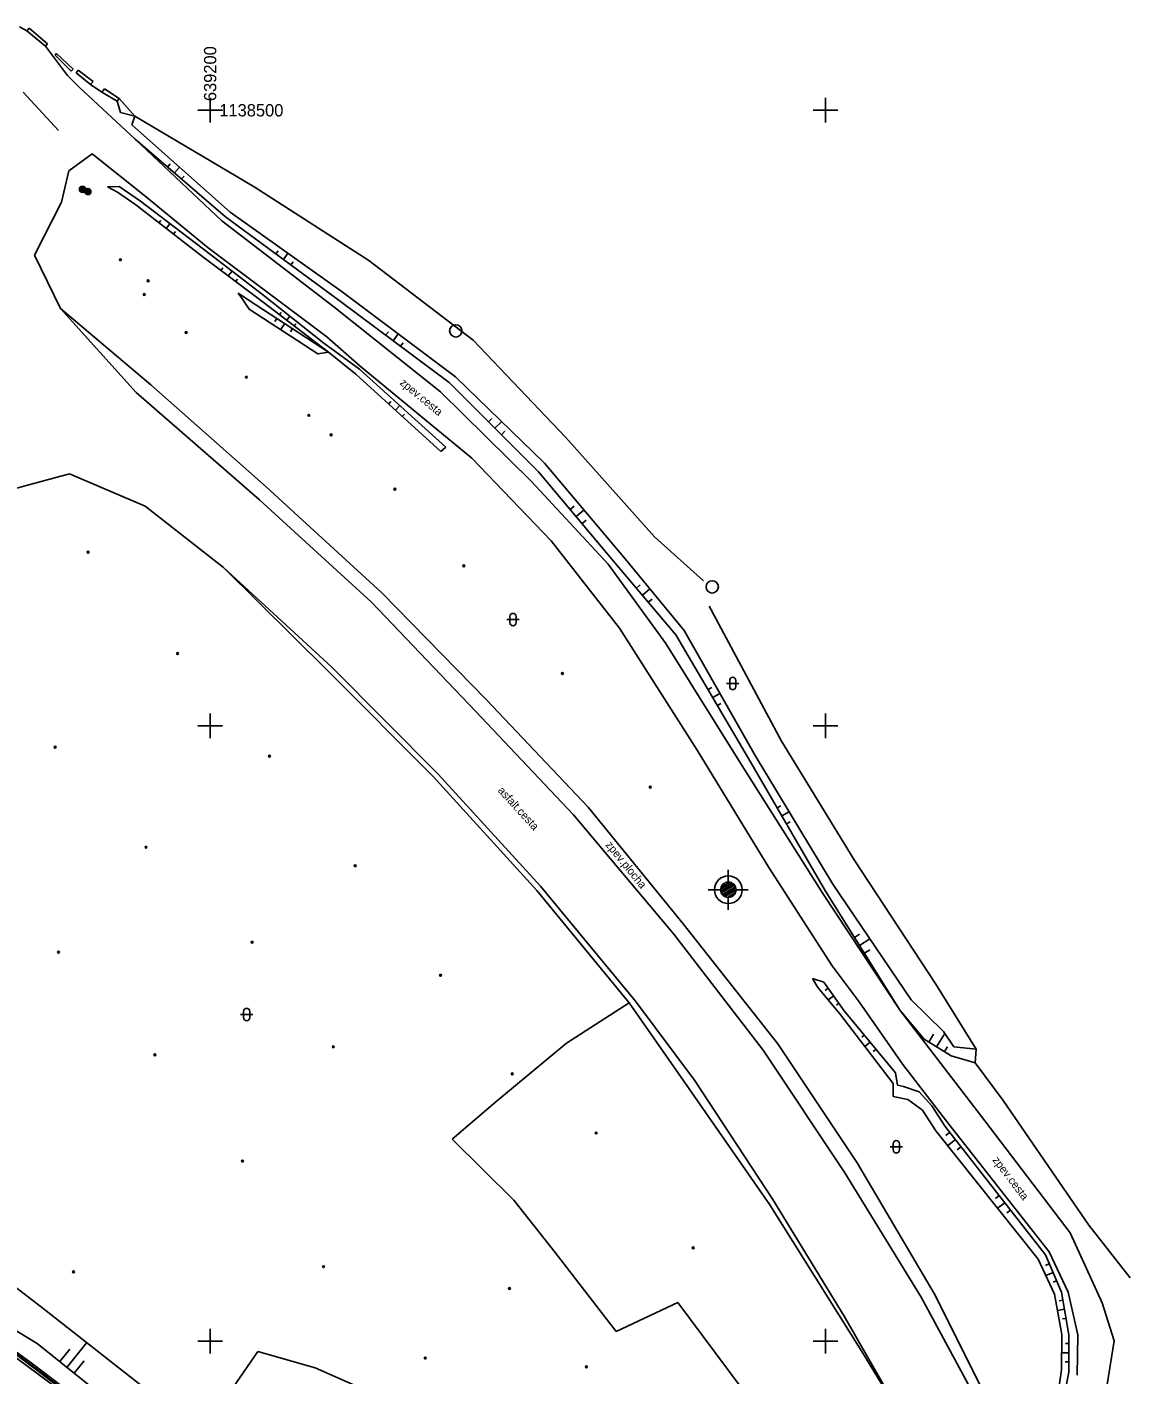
# Model space of a CAD drawing. Extents: x -639440 to -639026, y -1138850 to -1138262.
# Drawn here: x -639214.9 to -639125.9, y -1138602.7 to -1138493.2 of the extents above; entities that cross this region are included whole.
import ezdxf

# ---------------------------------------------------------------- set-up
doc = ezdxf.new("R2010")
doc.units = 0
for name, color, linetype in [('Vrstva 10', 7, 'Continuous'), ('Vrstva 11', 7, 'Continuous'), ('Vrstva 14', 7, 'Continuous'), ('Vrstva 15', 7, 'Continuous'), ('Vrstva 20', 7, 'Continuous'), ('Vrstva 23', 7, 'Continuous'), ('Vrstva 25', 7, 'Continuous'), ('Vrstva 27', 7, 'Continuous'), ('Vrstva 35', 7, 'Continuous'), ('Vrstva 36', 7, 'Continuous'), ('Vrstva 40', 7, 'Continuous'), ('Vrstva 58', 7, 'Continuous'), ('Vrstva 61', 7, 'Continuous'), ('Vrstva 7', 7, 'Continuous')]:
    doc.layers.add(name, color=color, linetype=linetype)

msp = doc.modelspace()

# ---------------------------------------------------------------- linework, layer by layer
at = {"layer": 'Vrstva 10'}
for p, q in [((-639215.48, -1138493.23), (-639214.88, -1138493.55)), ((-639214.88, -1138493.55), (-639213.38, -1138494.78)), ((-639213.38, -1138494.78), (-639211.58, -1138497.17)), ((-639211.58, -1138497.17), (-639210.63, -1138498.13)), ((-639210.63, -1138498.13), (-639206.08, -1138502.35)), ((-639206.08, -1138502.35), (-639199.05, -1138508.98)), ((-639209.58, -1138503.55), (-639211.49, -1138504.93)), ((-639205.3, -1138506.94), (-639209.58, -1138503.55)), ((-639211.49, -1138504.93), (-639212.07, -1138507.47)), ((-639212.07, -1138507.47), (-639214.27, -1138511.78)), ((-639200.16, -1138511.18), (-639205.3, -1138506.94)), ((-639199.05, -1138508.98), (-639189.95, -1138515.96)), ((-639214.27, -1138511.78), (-639212.15, -1138516.09)), ((-639190.53, -1138518.4), (-639200.16, -1138511.18)), ((-639212.15, -1138516.09), (-639206.02, -1138522.92)), ((-639189.95, -1138515.96), (-639181.28, -1138522.87)), ((-639187.8, -1138520.78), (-639190.53, -1138518.4)), ((-639178.73, -1138528.27), (-639187.8, -1138520.78)), ((-639206.02, -1138522.92), (-639195.99, -1138531.64)), ((-639181.28, -1138522.87), (-639173.89, -1138530.15)), ((-639172.29, -1138534.98), (-639178.73, -1138528.27)), ((-639211.43, -1138529.52), (-639218.24, -1138531.37)), ((-639205.27, -1138532.15), (-639211.43, -1138529.52)), ((-639173.89, -1138530.15), (-639167.67, -1138536.86)), ((-639198.92, -1138537.15), (-639205.27, -1138532.15)), ((-639195.99, -1138531.64), (-639186.89, -1138539.97)), ((-639166.75, -1138542.08), (-639172.29, -1138534.98)), ((-639167.67, -1138536.86), (-639162.97, -1138543.32)), ((-639190.1, -1138545.23), (-639198.92, -1138537.15)), ((-639186.89, -1138539.97), (-639178.43, -1138548.8)), ((-639160.44, -1138551.98), (-639166.75, -1138542.08)), ((-639162.97, -1138543.32), (-639156.9, -1138553.03)), ((-639181.47, -1138553.92), (-639190.1, -1138545.23)), ((-639178.43, -1138548.8), (-639170.48, -1138557.24)), ((-639154.62, -1138561.52), (-639160.44, -1138551.98)), ((-639156.9, -1138553.03), (-639150.22, -1138563.63)), ((-639173.16, -1138563.02), (-639181.47, -1138553.92)), ((-639170.48, -1138557.24), (-639162.34, -1138566.94)), ((-639149.45, -1138569.5), (-639154.62, -1138561.52)), ((-639165.45, -1138572.36), (-639173.16, -1138563.02)), ((-639150.22, -1138563.63), (-639143.93, -1138573.13)), ((-639162.34, -1138566.94), (-639155.06, -1138576.36)), ((-639147.28, -1138572.42), (-639149.45, -1138569.5)), ((-639160.65, -1138578.79), (-639165.45, -1138572.36)), ((-639143.73, -1138577.51), (-639147.28, -1138572.42)), ((-639143.93, -1138573.13), (-639137.06, -1138582.09)), ((-639155.06, -1138576.36), (-639148.43, -1138586.32)), ((-639139.98, -1138582.35), (-639143.73, -1138577.51)), ((-639154.29, -1138588.47), (-639160.65, -1138578.79)), ((-639131.83, -1138592.74), (-639139.98, -1138582.35)), ((-639137.06, -1138582.09), (-639130.12, -1138591.2)), ((-639148.43, -1138586.32), (-639142.24, -1138596.43)), ((-639148.48, -1138597.96), (-639154.29, -1138588.47)), ((-639130.12, -1138591.2), (-639127.53, -1138596.88)), ((-639130.29, -1138596), (-639131.83, -1138592.74)), ((-639129.5, -1138599.47), (-639130.29, -1138596)), ((-639142.24, -1138596.43), (-639136.62, -1138606.78)), ((-639127.53, -1138596.88), (-639126.56, -1138599.96)), ((-639143.51, -1138606.64), (-639148.48, -1138597.96)), ((-639129.57, -1138602.75), (-639129.5, -1138599.47)), ((-639126.56, -1138599.96), (-639127.11, -1138603.5))]:
    msp.add_line(p, q, dxfattribs=at)
at = {"layer": 'Vrstva 11'}
for p, q in [((-639214.69, -1138493.33), (-639214.88, -1138493.55)), ((-639214.69, -1138493.33), (-639213.21, -1138494.61)), ((-639213.21, -1138494.61), (-639213.38, -1138494.78)), ((-639212.6, -1138495.51), (-639212.48, -1138495.38)), ((-639212.48, -1138495.38), (-639211.13, -1138496.65)), ((-639211.3, -1138496.82), (-639212.6, -1138495.51)), ((-639211.13, -1138496.65), (-639211.3, -1138496.82)), ((-639210.88, -1138496.95), (-639210.71, -1138496.73)), ((-639209.71, -1138497.9), (-639210.88, -1138496.95)), ((-639210.71, -1138496.73), (-639209.51, -1138497.66)), ((-639209.51, -1138497.66), (-639209.71, -1138497.9)), ((-639208.79, -1138498.54), (-639208.58, -1138498.25)), ((-639208.58, -1138498.25), (-639207.38, -1138499.05)), ((-639207.38, -1138499.05), (-639207.56, -1138499.27)), ((-639165.96, -1138572.52), (-639171.06, -1138575.78)), ((-639171.06, -1138575.78), (-639176.79, -1138580.56)), ((-639176.79, -1138580.56), (-639180.33, -1138583.57)), ((-639180.33, -1138583.57), (-639175.33, -1138588.55)), ((-639175.33, -1138588.55), (-639171.97, -1138592.8)), ((-639171.97, -1138592.8), (-639167.02, -1138599.2)), ((-639167.02, -1138599.2), (-639162, -1138596.86)), ((-639162, -1138596.86), (-639153.43, -1138608.35)), ((-639214.65, -1138601.66), (-639218.03, -1138599.22)), ((-639196.13, -1138600.83), (-639198.4, -1138604.13)), ((-639191.46, -1138602.15), (-639196.13, -1138600.83)), ((-639205.13, -1138608.87), (-639214.65, -1138601.66)), ((-639184.91, -1138605.05), (-639191.46, -1138602.15))]:
    msp.add_line(p, q, dxfattribs=at)
at = {"layer": 'Vrstva 14'}
for p, q in [((-639209.71, -1138497.9), (-639208.79, -1138498.54)), ((-639208.79, -1138498.54), (-639207.56, -1138499.27)), ((-639207.56, -1138499.27), (-639207.27, -1138500.17)), ((-639206.13, -1138500.48), (-639207.38, -1138499.05)), ((-639207.27, -1138500.17), (-639206.13, -1138500.48)), ((-639206.13, -1138500.48), (-639206.36, -1138501.18)), ((-639206.13, -1138500.48), (-639196.43, -1138506.23)), ((-639206.36, -1138501.18), (-639198.37, -1138508.27)), ((-639206.08, -1138502.35), (-639198.75, -1138508.66)), ((-639207.39, -1138506.2), (-639208.34, -1138506.21)), ((-639207.53, -1138506.64), (-639208.34, -1138506.21)), ((-639205.67, -1138507.38), (-639207.39, -1138506.2)), ((-639196.43, -1138506.23), (-639187.11, -1138512.21)), ((-639206.03, -1138507.68), (-639207.53, -1138506.64)), ((-639200.08, -1138511.63), (-639205.67, -1138507.38)), ((-639200.6, -1138511.91), (-639206.03, -1138507.68)), ((-639198.37, -1138508.27), (-639189.26, -1138514.75)), ((-639198.75, -1138508.66), (-639189.53, -1138515.45)), ((-639195.75, -1138514.97), (-639200.08, -1138511.63)), ((-639195.68, -1138515.6), (-639200.6, -1138511.91)), ((-639187.11, -1138512.21), (-639178.63, -1138518.67)), ((-639196.29, -1138515.8), (-639197.71, -1138514.85)), ((-639197.43, -1138515.26), (-639197.71, -1138514.85)), ((-639190.77, -1138518.91), (-639195.75, -1138514.97)), ((-639189.26, -1138514.75), (-639180.06, -1138521.64)), ((-639196.83, -1138516.17), (-639197.43, -1138515.26)), ((-639191.26, -1138519.79), (-639196.83, -1138516.17)), ((-639190.37, -1138519.64), (-639196.29, -1138515.8)), ((-639190.37, -1138519.64), (-639195.68, -1138515.6)), ((-639189.53, -1138515.45), (-639180.58, -1138522.11)), ((-639187.87, -1138521.04), (-639190.77, -1138518.91)), ((-639178.63, -1138518.67), (-639171.09, -1138526.58)), ((-639190.37, -1138519.64), (-639191.26, -1138519.79)), ((-639188.15, -1138521.43), (-639190.37, -1138519.64)), ((-639181.27, -1138527.73), (-639188.15, -1138521.43)), ((-639180.85, -1138527.36), (-639187.87, -1138521.04)), ((-639180.06, -1138521.64), (-639172.83, -1138528.66)), ((-639180.58, -1138522.11), (-639173.32, -1138529.38)), ((-639171.09, -1138526.58), (-639163.89, -1138534.66)), ((-639180.85, -1138527.36), (-639181.27, -1138527.73)), ((-639172.83, -1138528.66), (-639166.27, -1138536.44)), ((-639173.32, -1138529.38), (-639167.22, -1138536.63)), ((-639163.89, -1138534.66), (-639159.91, -1138538.23)), ((-639167.22, -1138536.63), (-639162.16, -1138542.61)), ((-639166.27, -1138536.44), (-639161.49, -1138542.27)), ((-639190.4, -1138545.56), (-639198.92, -1138537.15)), ((-639159.45, -1138540.27), (-639159.3, -1138540.59)), ((-639159.3, -1138540.59), (-639153.57, -1138551.26)), ((-639161.49, -1138542.27), (-639155.71, -1138552.41)), ((-639162.16, -1138542.61), (-639156.25, -1138552.66)), ((-639181.87, -1138554.11), (-639190.4, -1138545.56)), ((-639153.57, -1138551.26), (-639147.68, -1138560.89)), ((-639156.25, -1138552.66), (-639150, -1138563.43)), ((-639155.71, -1138552.41), (-639149.41, -1138562.87)), ((-639173.47, -1138563.39), (-639181.87, -1138554.11)), ((-639147.68, -1138560.89), (-639141.03, -1138570.98)), ((-639149.41, -1138562.87), (-639143.04, -1138572.25)), ((-639165.96, -1138572.52), (-639173.47, -1138563.39)), ((-639150, -1138563.43), (-639143.93, -1138573.13)), ((-639150.13, -1138570.82), (-639151.07, -1138570.54)), ((-639150.63, -1138571.26), (-639151.07, -1138570.54)), ((-639148.48, -1138573.15), (-639150.13, -1138570.82)), ((-639148.84, -1138573.4), (-639150.63, -1138571.26)), ((-639141.03, -1138570.98), (-639137.76, -1138576.28)), ((-639161.96, -1138578.25), (-639165.96, -1138572.52)), ((-639143.93, -1138573.13), (-639142, -1138575.46)), ((-639143.04, -1138572.25), (-639140.43, -1138574.83)), ((-639144.52, -1138579.06), (-639148.84, -1138573.4)), ((-639144.31, -1138578.19), (-639148.48, -1138573.15)), ((-639140.43, -1138574.83), (-639139.57, -1138576.08)), ((-639142, -1138575.46), (-639139.79, -1138576.81)), ((-639139.57, -1138576.08), (-639137.76, -1138576.28)), ((-639137.76, -1138576.28), (-639137.84, -1138577.39)), ((-639139.79, -1138576.81), (-639137.84, -1138577.39)), ((-639137.84, -1138577.39), (-639135.57, -1138580.44)), ((-639154.53, -1138588.91), (-639161.96, -1138578.25)), ((-639144.15, -1138579.2), (-639144.31, -1138578.19)), ((-639144.51, -1138580.11), (-639144.52, -1138579.06)), ((-639143.66, -1138579.29), (-639144.15, -1138579.2)), ((-639143.66, -1138579.29), (-639142.39, -1138579.74)), ((-639144.51, -1138580.11), (-639143.31, -1138580.37)), ((-639143.31, -1138580.37), (-639142.13, -1138581.23)), ((-639142.39, -1138579.74), (-639141.36, -1138580.88)), ((-639135.57, -1138580.44), (-639128.62, -1138590.56)), ((-639142.13, -1138581.23), (-639141.05, -1138582.91)), ((-639140.29, -1138582.55), (-639141.36, -1138580.88)), ((-639132.72, -1138593.34), (-639141.05, -1138582.91)), ((-639132.14, -1138592.97), (-639140.29, -1138582.55)), ((-639147.06, -1138600.83), (-639154.53, -1138588.91)), ((-639128.62, -1138590.56), (-639125.26, -1138594.84)), ((-639213.7, -1138597.22), (-639221.6, -1138591.2)), ((-639131.41, -1138596.17), (-639132.72, -1138593.34)), ((-639130.83, -1138596), (-639132.14, -1138592.97)), ((-639130.23, -1138599.48), (-639130.83, -1138596)), ((-639130.79, -1138599.45), (-639131.41, -1138596.17)), ((-639202.39, -1138606.09), (-639213.7, -1138597.22)), ((-639216.32, -1138598.81), (-639214.05, -1138600.18)), ((-639214.05, -1138600.18), (-639204.07, -1138608.17)), ((-639130.82, -1138602.31), (-639130.79, -1138599.45)), ((-639130.23, -1138602.51), (-639130.23, -1138599.48)), ((-639143.51, -1138606.64), (-639147.06, -1138600.83)), ((-639131.57, -1138607.38), (-639130.82, -1138602.31)), ((-639131.22, -1138607.47), (-639130.23, -1138602.51))]:
    msp.add_line(p, q, dxfattribs=at)
at = {"layer": 'Vrstva 15'}
for p, q in [((-639203.46, -1138504.61), (-639203.25, -1138504.36)), ((-639202.89, -1138505.09), (-639202.48, -1138504.62)), ((-639202.32, -1138505.58), (-639202.12, -1138505.35)), ((-639204.16, -1138509.14), (-639204.01, -1138508.95)), ((-639203.57, -1138509.6), (-639203.26, -1138509.21)), ((-639202.97, -1138510.06), (-639202.82, -1138509.86)), ((-639194.66, -1138511.67), (-639194.47, -1138511.42)), ((-639194.05, -1138512.12), (-639193.68, -1138511.61)), ((-639199.13, -1138513.01), (-639198.97, -1138512.81)), ((-639193.45, -1138512.56), (-639193.26, -1138512.3)), ((-639198.53, -1138513.46), (-639198.22, -1138513.06)), ((-639197.93, -1138513.91), (-639197.78, -1138513.72)), ((-639194.57, -1138516.91), (-639194.74, -1138517.17)), ((-639194.36, -1138516.6), (-639194.24, -1138516.44)), ((-639193.94, -1138517.32), (-639194.27, -1138517.83)), ((-639193.77, -1138517.06), (-639193.52, -1138516.73)), ((-639193.31, -1138517.73), (-639193.48, -1138517.99)), ((-639193.17, -1138517.51), (-639193.05, -1138517.35)), ((-639185.74, -1138518.27), (-639185.52, -1138517.99)), ((-639185.13, -1138518.72), (-639184.71, -1138518.16)), ((-639184.53, -1138519.17), (-639184.32, -1138518.89)), ((-639185.49, -1138523.86), (-639185.32, -1138523.67)), ((-639184.94, -1138524.37), (-639184.59, -1138523.99)), ((-639184.39, -1138524.87), (-639184.21, -1138524.68)), ((-639177.39, -1138525.3), (-639177.12, -1138525.03)), ((-639176.86, -1138525.83), (-639176.31, -1138525.28)), ((-639176.33, -1138526.36), (-639176.05, -1138526.08)), ((-639170.75, -1138532.43), (-639170.43, -1138532.16)), ((-639170.27, -1138533.01), (-639169.62, -1138532.46)), ((-639169.78, -1138533.58), (-639169.46, -1138533.31)), ((-639165.37, -1138538.82), (-639165.06, -1138538.56)), ((-639164.88, -1138539.39), (-639164.27, -1138538.88)), ((-639164.4, -1138539.97), (-639164.1, -1138539.71)), ((-639159.54, -1138547.06), (-639159.25, -1138546.89)), ((-639159.16, -1138547.71), (-639158.58, -1138547.37)), ((-639158.78, -1138548.35), (-639158.5, -1138548.19)), ((-639153.92, -1138556.67), (-639153.64, -1138556.5)), ((-639153.55, -1138557.32), (-639152.96, -1138556.98)), ((-639153.17, -1138557.97), (-639152.87, -1138557.79)), ((-639147.64, -1138567.2), (-639147.23, -1138566.94)), ((-639147.24, -1138567.84), (-639146.4, -1138567.31)), ((-639146.84, -1138568.47), (-639146.41, -1138568.2)), ((-639149.78, -1138571.32), (-639150.03, -1138571.5)), ((-639149.34, -1138571.93), (-639149.8, -1138572.25)), ((-639148.91, -1138572.54), (-639149.11, -1138572.69)), ((-639146.85, -1138575.12), (-639147.06, -1138575.29)), ((-639141.62, -1138575.69), (-639141.23, -1138575.06)), ((-639140.98, -1138576.08), (-639140.32, -1138575)), ((-639146.37, -1138575.7), (-639146.81, -1138576.06)), ((-639145.89, -1138576.28), (-639146.12, -1138576.47)), ((-639140.34, -1138576.47), (-639140.1, -1138576.07)), ((-639139.92, -1138583.03), (-639140.24, -1138583.28)), ((-639139.45, -1138583.62), (-639140.09, -1138584.12)), ((-639138.99, -1138584.21), (-639139.31, -1138584.46)), ((-639135.9, -1138588.16), (-639136.2, -1138588.39)), ((-639135.44, -1138588.75), (-639136.02, -1138589.2)), ((-639134.98, -1138589.34), (-639135.27, -1138589.56)), ((-639131.82, -1138593.71), (-639132.12, -1138593.84)), ((-639131.52, -1138594.4), (-639132.11, -1138594.65)), ((-639131.23, -1138595.09), (-639131.51, -1138595.21)), ((-639130.72, -1138596.66), (-639131.01, -1138596.71)), ((-639130.59, -1138597.4), (-639131.16, -1138597.5)), ((-639130.46, -1138598.14), (-639130.74, -1138598.19)), ((-639211.63, -1138602.12), (-639210.02, -1138600.11)), ((-639130.23, -1138600.18), (-639130.51, -1138600.18)), ((-639212.22, -1138601.65), (-639211.41, -1138600.65)), ((-639211.04, -1138602.59), (-639210.24, -1138601.58)), ((-639130.23, -1138600.93), (-639130.81, -1138600.93)), ((-639130.23, -1138601.68), (-639130.52, -1138601.68))]:
    msp.add_line(p, q, dxfattribs=at)
at = {"layer": 'Vrstva 20'}
for centre, radius in [((-639207.29, -1138512.14), 0.075), ((-639207.29, -1138512.14), 0.0204), ((-639205.04, -1138513.85), 0.075), ((-639205.04, -1138513.85), 0.0204), ((-639205.35, -1138514.97), 0.075), ((-639205.35, -1138514.97), 0.0204), ((-639201.95, -1138518.05), 0.075), ((-639201.95, -1138518.05), 0.0204), ((-639197.06, -1138521.68), 0.075), ((-639197.06, -1138521.68), 0.0204), ((-639191.98, -1138524.78), 0.075), ((-639191.98, -1138524.78), 0.0204), ((-639190.17, -1138526.37), 0.075), ((-639190.17, -1138526.37), 0.0204), ((-639184.99, -1138530.78), 0.075), ((-639184.99, -1138530.78), 0.0204), ((-639209.92, -1138535.9), 0.075), ((-639209.92, -1138535.9), 0.0204), ((-639179.39, -1138537), 0.075), ((-639179.39, -1138537), 0.0204), ((-639202.64, -1138544.13), 0.075), ((-639202.64, -1138544.13), 0.0204), ((-639171.38, -1138545.75), 0.075), ((-639171.38, -1138545.75), 0.0204), ((-639212.59, -1138551.74), 0.075), ((-639212.59, -1138551.74), 0.0204), ((-639195.18, -1138552.47), 0.075), ((-639195.18, -1138552.47), 0.0204), ((-639164.24, -1138554.98), 0.075), ((-639164.24, -1138554.98), 0.0204), ((-639205.21, -1138559.87), 0.075), ((-639205.21, -1138559.87), 0.0204), ((-639188.21, -1138561.37), 0.075), ((-639188.21, -1138561.37), 0.0204), ((-639196.59, -1138567.59), 0.075), ((-639196.59, -1138567.59), 0.0204), ((-639212.32, -1138568.39), 0.075), ((-639212.32, -1138568.39), 0.0204), ((-639181.28, -1138570.27), 0.075), ((-639181.28, -1138570.27), 0.0204), ((-639189.99, -1138576.08), 0.075), ((-639189.99, -1138576.08), 0.0204), ((-639204.49, -1138576.73), 0.075), ((-639204.49, -1138576.73), 0.0204), ((-639175.45, -1138578.28), 0.075), ((-639175.45, -1138578.28), 0.0204), ((-639168.63, -1138583.08), 0.075), ((-639168.63, -1138583.08), 0.0204), ((-639197.37, -1138585.36), 0.075), ((-639197.37, -1138585.36), 0.0204), ((-639160.75, -1138592.41), 0.075), ((-639160.75, -1138592.41), 0.0204), ((-639190.78, -1138593.94), 0.075), ((-639190.78, -1138593.94), 0.0204), ((-639211.1, -1138594.36), 0.075), ((-639211.1, -1138594.36), 0.0204), ((-639175.68, -1138595.71), 0.075), ((-639175.68, -1138595.71), 0.0204), ((-639182.52, -1138601.36), 0.075), ((-639182.52, -1138601.36), 0.0204), ((-639169.43, -1138602.08), 0.075), ((-639169.43, -1138602.08), 0.0204)]:
    msp.add_circle(centre, radius, dxfattribs=at)
at = {"layer": 'Vrstva 23'}
for p, q in [((-639212.15, -1138516.09), (-639204.81, -1138522.29)), ((-639204.81, -1138522.29), (-639195.44, -1138530.6)), ((-639195.44, -1138530.6), (-639186.06, -1138539.2)), ((-639186.06, -1138539.2), (-639177.56, -1138547.89)), ((-639177.56, -1138547.89), (-639169.28, -1138556.61)), ((-639169.28, -1138556.61), (-639161.58, -1138566.09)), ((-639161.58, -1138566.09), (-639153.89, -1138575.84)), ((-639153.89, -1138575.84), (-639147.44, -1138585.5)), ((-639147.44, -1138585.5), (-639141.18, -1138596.13)), ((-639141.18, -1138596.13), (-639136.06, -1138606.3))]:
    msp.add_line(p, q, dxfattribs=at)
at = {"layer": 'Vrstva 25'}
for centre, radius in [((-639210.37, -1138506.43), 0.25), ((-639210.37, -1138506.43), 0.2), ((-639210.37, -1138506.43), 0.15), ((-639210.37, -1138506.43), 0.1), ((-639210.37, -1138506.43), 0.05), ((-639209.93, -1138506.6), 0.25), ((-639209.93, -1138506.6), 0.2), ((-639209.93, -1138506.6), 0.15), ((-639209.93, -1138506.6), 0.1), ((-639209.93, -1138506.6), 0.05)]:
    msp.add_circle(centre, radius, dxfattribs=at)
at = {"layer": 'Vrstva 27'}
for centre in [(-639180.04, -1138517.92), (-639159.21, -1138538.72)]:
    msp.add_circle(centre, 0.5, dxfattribs=at)
at = {"layer": 'Vrstva 35'}
for p, q in [((-639157.9, -1138562.7), (-639157.9, -1138561.7)), ((-639158.52, -1138563.28), (-639157.62, -1138562.76)), ((-639158.51, -1138563.44), (-639157.49, -1138562.85)), ((-639158.48, -1138563.1), (-639157.8, -1138562.7)), ((-639158.47, -1138563.57), (-639157.39, -1138562.95)), ((-639158.4, -1138563.7), (-639157.33, -1138563.07)), ((-639158.3, -1138563.8), (-639157.29, -1138563.21)), ((-639158.53, -1138563.32), (-639159.53, -1138563.32)), ((-639158.17, -1138563.88), (-639157.28, -1138563.37)), ((-639157.98, -1138563.94), (-639157.32, -1138563.56)), ((-639157.9, -1138563.95), (-639157.9, -1138564.95)), ((-639157.28, -1138563.32), (-639156.28, -1138563.32))]:
    msp.add_line(p, q, dxfattribs=at)
for radius in [1.12, 0.625]:
    msp.add_circle((-639157.9, -1138563.32), radius, dxfattribs=at)
at = {"layer": 'Vrstva 36'}
for p, q in [((-639175.89, -1138541.37), (-639174.89, -1138541.37)), ((-639175.64, -1138541.12), (-639175.64, -1138541.62)), ((-639175.14, -1138541.12), (-639175.14, -1138541.62)), ((-639158.04, -1138546.56), (-639157.04, -1138546.56)), ((-639157.79, -1138546.31), (-639157.79, -1138546.81)), ((-639157.29, -1138546.31), (-639157.29, -1138546.81)), ((-639197.53, -1138573.46), (-639196.53, -1138573.46)), ((-639197.28, -1138573.21), (-639197.28, -1138573.71)), ((-639196.78, -1138573.21), (-639196.78, -1138573.71)), ((-639144.5, -1138583.95), (-639144.5, -1138584.45)), ((-639144, -1138583.95), (-639144, -1138584.45)), ((-639144.75, -1138584.2), (-639143.75, -1138584.2))]:
    msp.add_line(p, q, dxfattribs=at)
for centre, start, end in [((-639175.39, -1138541.12), 0, 180), ((-639175.39, -1138541.62), 180, 0), ((-639157.54, -1138546.31), 0, 180), ((-639157.54, -1138546.81), 180, 0), ((-639197.03, -1138573.21), 0, 180), ((-639197.03, -1138573.71), 180, 0), ((-639144.25, -1138583.95), 0, 180), ((-639144.25, -1138584.45), 180, 0)]:
    msp.add_arc(centre, 0.25, start, end, dxfattribs=at)
at = {"layer": 'Vrstva 58'}
msp.add_line((-639215.19, -1138498.54), (-639212.32, -1138501.63), dxfattribs=at)
at = {"layer": 'Vrstva 61'}
for p, q in [((-639200, -1138499), (-639200, -1138501)), ((-639150, -1138499), (-639150, -1138501)), ((-639201, -1138500), (-639199, -1138500)), ((-639151, -1138500), (-639149, -1138500)), ((-639200, -1138549), (-639200, -1138551)), ((-639150, -1138549), (-639150, -1138551)), ((-639201, -1138550), (-639199, -1138550)), ((-639151, -1138550), (-639149, -1138550)), ((-639200, -1138599), (-639200, -1138601)), ((-639150, -1138599), (-639150, -1138601)), ((-639201, -1138600), (-639199, -1138600)), ((-639151, -1138600), (-639149, -1138600))]:
    msp.add_line(p, q, dxfattribs=at)
at = {"layer": 'Vrstva 7'}
for p, q in [((-639210.94, -1138604.92), (-639216.37, -1138600.89)), ((-639190.04, -1138620.41), (-639216.21, -1138600.66)), ((-639210.95, -1138604.73), (-639216.2, -1138600.75))]:
    msp.add_line(p, q, dxfattribs=at)

# ---------------------------------------------------------------- texts
at = {"layer": 'Vrstva 40'}
for s, rotation, p in [('zpev.cesta', 320.4501, (-639184.64, -1138522.22)), ('asfalt.cesta', 312.4019, (-639176.67, -1138555.3)), ('zpev.plocha', 309.0848, (-639167.91, -1138559.69)), ('zpev.cesta', 307.3002, (-639136.47, -1138585.29))]:
    msp.add_text(s, height=0.65, rotation=rotation, dxfattribs=at).set_placement(p)
at = {"layer": 'Vrstva 61'}
msp.add_text('  639200', height=1, rotation=90, dxfattribs=at).set_placement((-639199.5, -1138500))
msp.add_text('  1138500', height=1, dxfattribs=at).set_placement((-639200, -1138500.5))

doc.saveas('drawing.dxf')
